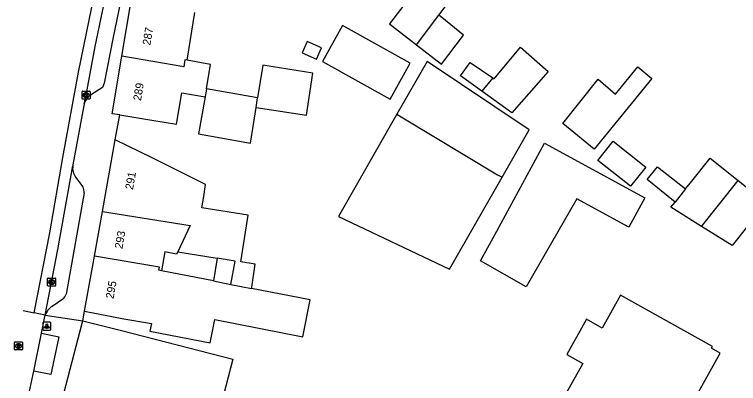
# Model space of a CAD drawing. Extents: x 160158 to 160921, y 381517 to 382041.
# Drawn here: x 160275 to 160365.5, y 381838.6 to 381884.7 of the extents above; entities that cross this region are included whole.
import ezdxf

# ---------------------------------------------------------------- set-up
doc = ezdxf.new("R2010")
doc.units = 0
for name, color, linetype in [('IMGEO_Kolk', 7, 'Continuous'), ('IMGEO_Lichtpunt', 7, 'Continuous'), ('IMGEO_Pand', 7, 'Continuous'), ('IMGEO_Pand_nummerreeks', 7, 'Continuous'), ('IMGEO_Rijbaan_lokaal_gesloten', 7, 'Continuous'), ('IMGEO_Rioolput', 7, 'Continuous'), ('IMGEO_Voetpad_open', 7, 'Continuous')]:
    doc.layers.add(name, color=color, linetype=linetype)

msp = doc.modelspace()

# ---------------------------------------------------------------- linework, layer by layer
at = {"layer": 'IMGEO_Kolk'}
for p, q in [((160283.462, 381874.179), (160283.462, 381875.031)), ((160283.537, 381875.105), (160284.389, 381875.105)), ((160283.95, 381874.885), (160283.975, 381874.885)), ((160284.463, 381875.031), (160284.463, 381874.179)), ((160284.389, 381874.105), (160283.537, 381874.105)), ((160283.973, 381874.325), (160283.948, 381874.325)), ((160279.165, 381850.824), (160279.165, 381851.676)), ((160279.24, 381851.75), (160280.092, 381851.75)), ((160279.653, 381851.53), (160279.678, 381851.53)), ((160280.166, 381851.676), (160280.166, 381850.824)), ((160280.092, 381850.75), (160279.24, 381850.75)), ((160279.676, 381850.97), (160279.651, 381850.97))]:
    msp.add_line(p, q, dxfattribs=at)
for points in [[(160283.462, 381874.179), (160283.462, 381875.031)], [(160283.537, 381875.105), (160284.389, 381875.105)], [(160284.463, 381875.031), (160284.463, 381874.179)], [(160284.389, 381874.105), (160283.537, 381874.105)], [(160283.783, 381874.805), (160283.906, 381874.805), (160283.906, 381874.654), (160284.036, 381874.805), (160284.2, 381874.805), (160284.054, 381874.654), (160284.207, 381874.405), (160284.055, 381874.405), (160283.97, 381874.569), (160283.906, 381874.502), (160283.906, 381874.405), (160283.783, 381874.405), (160283.783, 381874.805)], [(160279.165, 381850.824), (160279.165, 381851.676)], [(160279.24, 381851.75), (160280.092, 381851.75)], [(160279.486, 381851.45), (160279.609, 381851.45), (160279.609, 381851.299), (160279.739, 381851.45), (160279.903, 381851.45), (160279.757, 381851.299), (160279.91, 381851.05), (160279.758, 381851.05), (160279.673, 381851.214), (160279.609, 381851.147), (160279.609, 381851.05), (160279.486, 381851.05), (160279.486, 381851.45)], [(160280.166, 381851.676), (160280.166, 381850.824)], [(160280.092, 381850.75), (160279.24, 381850.75)]]:
    msp.add_lwpolyline(points, dxfattribs=at)
for centre, start, end in [((160283.539, 381875.029), 91.55205, 178.44795), ((160283.539, 381875.029), 91.55205, 178.44795), ((160284.387, 381875.029), 1.55205, 88.44795), ((160284.387, 381875.029), 1.55205, 88.44795), ((160283.539, 381874.181), 181.55205, 268.44795), ((160283.539, 381874.181), 181.55205, 268.44795), ((160284.387, 381874.181), 271.55205, 358.44795), ((160284.387, 381874.181), 271.55205, 358.44795), ((160279.242, 381851.674), 91.55205, 178.44795), ((160279.242, 381851.674), 91.55205, 178.44795), ((160280.09, 381851.674), 1.55205, 88.44795), ((160280.09, 381851.674), 1.55205, 88.44795), ((160279.242, 381850.826), 181.55205, 268.44795), ((160279.242, 381850.826), 181.55205, 268.44795), ((160280.09, 381850.826), 271.55205, 358.44795), ((160280.09, 381850.826), 271.55205, 358.44795)]:
    msp.add_arc(centre, 0.0765, start, end, dxfattribs=at)
for centre, major_axis, ratio, start_param, end_param in [((160283.949, 381874.605), (-0.387, 0.002), 0.722429, 4.712389, 7.853982), ((160283.974, 381874.605), (-0.39, 0.002), 0.717154, 1.570796, 4.712389), ((160279.652, 381851.25), (-0.387, 0.002), 0.722429, 4.712389, 7.853982), ((160279.677, 381851.25), (-0.39, 0.002), 0.717154, 1.570796, 4.712389)]:
    msp.add_ellipse(centre, major_axis=major_axis, ratio=ratio, start_param=start_param, end_param=end_param, dxfattribs=at)
at = {"layer": 'IMGEO_Lichtpunt'}
for p, q in [((160278.57, 381846.138), (160278.57, 381845.331)), ((160278.57, 381846.138), (160278.57, 381845.331)), ((160279.472, 381846.233), (160278.664, 381846.233)), ((160279.472, 381846.233), (160278.664, 381846.233)), ((160279.566, 381845.331), (160279.566, 381846.138)), ((160279.566, 381845.331), (160279.566, 381846.138)), ((160278.664, 381845.237), (160279.472, 381845.237)), ((160278.664, 381845.237), (160279.472, 381845.237))]:
    msp.add_line(p, q, dxfattribs=at)
for points in [[(160278.944, 381845.802), (160278.983, 381845.774), (160278.795, 381845.512), (160278.757, 381845.539), (160278.944, 381845.802)], [(160279.046, 381845.754), (160279.093, 381845.754), (160279.093, 381845.432), (160279.046, 381845.432), (160279.046, 381845.754)], [(160279.156, 381845.774), (160279.194, 381845.801), (160279.381, 381845.539), (160279.342, 381845.511), (160279.156, 381845.774)]]:
    msp.add_lwpolyline(points, dxfattribs=at)
msp.add_circle((160279.069, 381845.936), 0.0994, dxfattribs=at)
for centre, start, end in [((160278.664, 381846.138), 90, 180), ((160278.664, 381846.138), 90, 180), ((160279.472, 381846.138), 0, 90), ((160279.472, 381846.138), 0, 90), ((160278.664, 381845.331), 180, 270), ((160278.664, 381845.331), 180, 270), ((160279.472, 381845.331), 270, 0), ((160279.472, 381845.331), 270, 360)]:
    msp.add_arc(centre, 0.0946, start, end, dxfattribs=at)
at = {"layer": 'IMGEO_Pand'}
for points in [[(160328.036, 381884.601), (160329.5, 381886.546), (160326.132, 381889.086), (160321.871, 381883.516), (160325.245, 381880.895)], [(160288.451, 381879.486), (160289.614, 381886.39)], [(160296.593, 381878.952), (160297.568, 381884.917)], [(160325.245, 381880.895), (160328.036, 381884.601)], [(160325.245, 381880.895), (160328.385, 381878.456), (160331.133, 381882.098), (160328.41, 381884.299), (160328.036, 381884.601)], [(160313.494, 381878.792), (160321.964, 381874.111), (160324.464, 381878.61), (160315.993, 381883.315), (160313.494, 381878.792)], [(160312.775, 381879.093), (160313.404, 381880.501), (160311.6, 381881.308), (160310.971, 381879.901), (160312.775, 381879.093)], [(160334.794, 381876.773), (160334.972, 381876.654), (160338.245, 381880.6), (160341.702, 381877.566), (160337.145, 381872.373), (160333.406, 381875.096)], [(160288.207, 381872.123), (160287.237, 381872.281), (160288.451, 381879.486)], [(160296.593, 381878.952), (160296.313, 381878.998), (160296.176, 381878.157), (160288.451, 381879.486)], [(160299.006, 381875.371), (160299.536, 381878.446), (160296.593, 381878.952)], [(160335.936, 381864.334), (160339.308, 381870.247), (160326.573, 381878.786), (160322.813, 381872.219)], [(160333.406, 381875.096), (160330.765, 381877.019), (160331.966, 381878.669), (160334.794, 381876.773)], [(160305.216, 381873.074), (160311.49, 381872.082), (160312.321, 381877.342), (160306.047, 381878.333), (160305.401, 381874.245)], [(160347.447, 381867.865), (160343.542, 381871.064), (160347.941, 381876.592), (160350.129, 381874.733), (160352.904, 381878.121), (160354.667, 381876.677), (160347.447, 381867.865)], [(160334.794, 381876.773), (160333.406, 381875.096)], [(160288.207, 381872.123), (160292.173, 381871.477), (160295.289, 381870.97), (160295.929, 381874.886), (160298.833, 381874.386)], [(160299.006, 381875.371), (160298.833, 381874.386)], [(160305.401, 381874.245), (160299.006, 381875.371)], [(160298.833, 381874.386), (160298.019, 381869.764), (160304.512, 381868.621), (160305.216, 381873.074)], [(160305.216, 381873.074), (160305.401, 381874.245)], [(160322.813, 381872.219), (160315.495, 381859.436), (160329.389, 381852.855), (160335.936, 381864.334)], [(160322.813, 381872.219), (160323.343, 381871.901), (160335.387, 381864.664), (160335.936, 381864.334)], [(160286.017, 381860.074), (160287.615, 381869.031)], [(160304.637, 381850.461), (160304.665, 381850.631), (160305.117, 381853.472), (160303.308, 381853.76), (160304.237, 381859.589), (160298.435, 381860.515), (160298.664, 381861.951), (160298.898, 381863.424), (160292.303, 381866.733), (160287.615, 381869.031)], [(160345.275, 381861.665), (160338.966, 381850.644), (160333.263, 381853.908), (160335.283, 381857.627), (160341.238, 381868.59), (160353.778, 381861.779), (160351.776, 381858.092), (160345.275, 381861.665)], [(160347.915, 381866.454), (160349.816, 381868.85), (160353.897, 381865.613), (160351.997, 381863.217), (160347.915, 381866.454)], [(160358.865, 381862.879), (160359.651, 381863.863), (160361.937, 381866.726), (160365.435, 381863.933)], [(160357.559, 381861.244), (160354.075, 381864.043), (160355.377, 381865.664), (160358.865, 381862.879)], [(160365.435, 381863.933), (160368.934, 381861.139), (160364.683, 381855.815), (160360.865, 381858.209)], [(160360.865, 381858.209), (160365.435, 381863.933)], [(160358.865, 381862.879), (160357.559, 381861.244)], [(160360.865, 381858.209), (160357.047, 381860.603), (160357.559, 381861.244)], [(160285.021, 381854.491), (160286.017, 381860.074)], [(160286.017, 381860.074), (160296.966, 381858.328), (160295.415, 381855.019)], [(160295.415, 381855.019), (160295.288, 381854.747), (160293.824, 381855.047), (160293.375, 381852.671)], [(160295.415, 381855.019), (160300.335, 381854.234)], [(160283.791, 381847.596), (160285.021, 381854.491)], [(160293.375, 381852.671), (160293.075, 381852.728), (160293.144, 381853.093), (160285.021, 381854.491)], [(160300.335, 381854.234), (160299.882, 381851.394)], [(160302.062, 381850.966), (160302.591, 381853.874), (160300.335, 381854.234)], [(160299.882, 381851.394), (160293.375, 381852.671)], [(160299.882, 381851.394), (160302.062, 381850.966)], [(160283.791, 381847.596), (160288.705, 381846.67), (160292.13, 381846.074), (160291.953, 381845.137), (160299.488, 381843.658), (160300.062, 381846.583), (160311.072, 381844.422), (160311.975, 381849.021), (160304.637, 381850.461)], [(160302.062, 381850.966), (160304.637, 381850.461)], [(160359.845, 381836.375), (160363.207, 381842.379), (160362.118, 381842.988), (160362.232, 381843.19), (160350.755, 381849.616), (160348.454, 381845.506), (160346.492, 381846.604), (160344.032, 381842.21), (160346.018, 381841.098), (160338.079, 381826.92), (160350.388, 381820.027), (160350.563, 381819.93), (160350.803, 381819.795), (160353.471, 381824.559), (160353.287, 381824.662), (160355.131, 381827.956)], [(160277.479, 381823.123), (160283.485, 381846.106), (160283.566, 381846.417)], [(160283.566, 381846.417), (160288.386, 381845.183), (160302.324, 381841.614), (160297.005, 381821.198)]]:
    msp.add_lwpolyline(points, dxfattribs=at)
at = {"layer": 'IMGEO_Rijbaan_lokaal_gesloten'}
for points in [[(160277.474, 381847.414), (160279.431, 381857.399), (160281.062, 381866.83), (160283.011, 381877.485), (160287.95, 381901.47), (160291.032, 381915.39), (160292.664, 381923.46), (160295.111, 381937.88), (160297.516, 381953.389), (160298.833, 381953.198)], [(160283.735, 381873.47), (160283.963, 381874.604), (160285.12, 381880.658), (160287.034, 381889.881), (160287.643, 381893.136)], [(160283.735, 381873.47), (160283.703, 381873.313), (160282.335, 381865.883), (160282.317, 381865.784)], [(160278.871, 381847.11), (160280.447, 381855.336), (160282.317, 381865.784)], [(160276.109, 381847.711), (160277.474, 381847.414)], [(160278.871, 381847.11), (160277.474, 381847.414)], [(160278.399, 381844.865), (160278.829, 381846.968), (160278.871, 381847.11)], [(160277.427, 381840.116), (160278.399, 381844.865)], [(160276.913, 381837.606), (160277.427, 381840.116)]]:
    msp.add_lwpolyline(points, dxfattribs=at)
at = {"layer": 'IMGEO_Rioolput'}
for p, q in [((160275.026, 381842.843), (160275.026, 381843.695)), ((160275.101, 381843.769), (160275.953, 381843.769)), ((160275.514, 381843.549), (160275.539, 381843.549)), ((160276.027, 381843.695), (160276.027, 381842.843)), ((160275.953, 381842.769), (160275.101, 381842.769)), ((160275.537, 381842.989), (160275.512, 381842.989))]:
    msp.add_line(p, q, dxfattribs=at)
for points in [[(160275.026, 381842.843), (160275.026, 381843.695)], [(160275.101, 381843.769), (160275.953, 381843.769)], [(160275.615, 381843.467), (160275.363, 381843.469), (160275.363, 381843.069)], [(160275.363, 381843.069), (160275.487, 381843.069), (160275.487, 381843.231), (160275.498, 381843.231)], [(160275.541, 381843.388), (160275.487, 381843.388), (160275.487, 381843.307)], [(160275.487, 381843.307), (160275.539, 381843.307)], [(160275.545, 381843.202), (160275.616, 381843.069), (160275.756, 381843.069), (160275.691, 381843.195)], [(160276.027, 381843.695), (160276.027, 381842.843)], [(160275.953, 381842.769), (160275.101, 381842.769)]]:
    msp.add_lwpolyline(points, dxfattribs=at)
for centre, radius, start, end in [((160275.103, 381843.693), 0.0765, 91.55205, 178.44795), ((160275.103, 381843.693), 0.0765, 91.55205, 178.44795), ((160275.497, 381843.178), 0.0533, 26.02933, 88.69889), ((160275.523, 381843.496), 0.19, 274.7715, 282.96867), ((160275.547, 381843.292), 0.0964, 77.00612, 93.18647), ((160275.561, 381843.349), 0.0378, 276.66336, 79.67722), ((160275.614, 381843.357), 0.109, 350.36119, 89.41601), ((160275.612, 381843.357), 0.112, 277.58423, 350.98172), ((160275.596, 381843.142), 0.108, 29.51342, 73.79051), ((160275.951, 381843.693), 0.0765, 1.55205, 88.44795), ((160275.951, 381843.693), 0.0765, 1.55205, 88.44795), ((160275.103, 381842.845), 0.0765, 181.55205, 268.44795), ((160275.103, 381842.845), 0.0765, 181.55205, 268.44795), ((160275.951, 381842.845), 0.0765, 271.55205, 358.44795), ((160275.951, 381842.845), 0.0765, 271.55205, 358.44795)]:
    msp.add_arc(centre, radius, start, end, dxfattribs=at)
for centre, major_axis, ratio, start_param, end_param in [((160275.513, 381843.269), (-0.387, 0.002), 0.722429, 4.712389, 7.853982), ((160275.538, 381843.269), (-0.39, 0.002), 0.717154, 1.570796, 4.712389)]:
    msp.add_ellipse(centre, major_axis=major_axis, ratio=ratio, start_param=start_param, end_param=end_param, dxfattribs=at)
at = {"layer": 'IMGEO_Voetpad_open'}
for points in [[(160287.951, 381891.763), (160288.831, 381890.459), (160288.944, 381890.105), (160288.99, 381889.709), (160287.357, 381881.84), (160286.246, 381876.114), (160286.007, 381875.539), (160284.523, 381874.601)], [(160287.615, 381869.031), (160288.207, 381872.123)], [(160282.659, 381864.36), (160283.547, 381863.13)], [(160283.718, 381862.412), (160281.464, 381849.758)], [(160281.07, 381849.126), (160279.73, 381848.203)], [(160278.871, 381847.11), (160283.566, 381846.417)], [(160283.566, 381846.417), (160283.791, 381847.596)], [(160278.399, 381844.865), (160280.566, 381844.421), (160279.581, 381839.697), (160277.427, 381840.116)]]:
    msp.add_lwpolyline(points, dxfattribs=at)
for centre, radius, start, end in [((160285.597, 381873.013), 1.917, 124.06504, 166.2029), ((160284.227, 381865.49), 1.933, 171.2434, 215.76633), ((160282.711, 381862.552), 1.016, 352.10425, 34.68794), ((160280.385, 381849.992), 1.105, 308.35844, 347.76127), ((160280.851, 381846.438), 2.091, 122.41678, 161.25487)]:
    msp.add_arc(centre, radius, start, end, dxfattribs=at)

# ---------------------------------------------------------------- texts
at = {"layer": 'IMGEO_Pand_nummerreeks'}
for s, rotation, p in [('287', 80.43889, (160291.994, 381880.779)), ('289', 80.43754, (160290.827, 381873.844)), ('291', 79.88751, (160289.823, 381862.731)), ('293', 79.88751, (160288.506, 381855.35)), ('295', 79.88751, (160287.393, 381849.111))]:
    msp.add_text(s, height=1, rotation=rotation, dxfattribs=at).set_placement(p)

doc.saveas('drawing.dxf')
